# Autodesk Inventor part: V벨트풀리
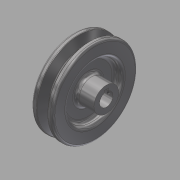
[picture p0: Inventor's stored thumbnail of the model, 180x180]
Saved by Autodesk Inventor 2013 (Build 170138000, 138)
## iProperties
Created: 2015-11
Part Number: V벨트풀리
Material: 강철, 탄소
Document SubType Name: Modeling
Designer: mduedu
Density: 1 g/cm^3
Author: mduedu
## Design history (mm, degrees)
sketch "스케치1"
  geometry: L1 (-9.5, 0)-(9.5, 0); L2 (0, 0)-(0, 37.7); L3 (-4.825, 37.7)-(-9.5, 37.7); L4 (-9.5, 37.7)-(-9.5, 0); L5 (0, 28.7)-(-2.074, 28.7); L6 (-2.074, 28.7)-(-4.825, 37.7); L7 (4.825, 37.7)-(9.5, 37.7); L8 (9.5, 37.7)-(9.5, 0); L9 (0, 28.7)-(2.074, 28.7); L10 (2.074, 28.7)-(4.825, 37.7); L11 (-9.5, 35)-(9.5, 35); 3 further points
  constraints: 22 end point, 7 point on line, 4 perpendicular, 3 symmetric about line, 1 coincident, 1 horizontal, 1 horizontal alignment, 1 midpoint, 1 vertical
  dimensions: "d0" = 19 distance of L1.start L1.end; "d2" = 75.4 diameter of L2.end L1 (derived); "d3" = 34 deg angle of L10 L6; "d4" = 6.3 distance between parallel lines of L11 L9; "d5" = 2.7 distance between parallel lines of L7 L11; "d6" = 8 distance of point (4, 35) point (-4, 35); "d7" = 70 diameter of L11 L1
revolve "회전1" sketch "스케치1" stored, may be unused: angle "d8" = 90 deg
sketch "스케치2"
  geometry: C1 r 24 at (0, 0); C2 r 11 at (0, 0); 1 further point
  constraints: 2 centre point, 2 coincident
  dimensions: "d9" = 48 diameter of C1; "d10" = 22 diameter of C2
extrude "돌출1" cut sketch "스케치2" distance "d11" = 6; taper "d12" = 0 deg
extrude "돌출3" join sketch "스케치2" distance "d37" = 10; taper "d38" = 0 deg
fillet "모깎기1" dims "d13" = 3
fillet "모깎기2" dims "d14" = 3
fillet "모깎기3" dims "d15" = 1, "d16" = 0.5, "d17" = 2
hole "구멍1" diameter "d20" = 12; stored, may be unused: countersink angle "d24" = 90 deg, drill point angle "d26" = 118 deg; dims "d21" = 6, "d22" = 4, "d23" = 2, "d25" = 8, "d39" = 10, "d40" = 10
sketch "스케치3"
  geometry: L1 (-2, 0)-(2, 0); L2 (2, 0)-(2, 7.8); L3 (2, 7.8)-(-2, 7.8); L4 (-2, 7.8)-(-2, 0); 2 further points
  constraints: 8 end point, 2 parallel, 1 coincident, 1 horizontal, 1 midpoint, 1 perpendicular
  dimensions: "d27" = 4 distance of L2.end L3.end; "d29" = 7.8 distance of L3.end L1.start
extrude "돌출2" cut sketch "스케치3" stored distance "d30" = 6; taper "d31" = 0 deg
chamfer "모따기1" distance "d32" = 0.5; stored, may be unused: second distance "d33" = 2, angle "d34" = 45 deg
node "작업 평면1"
sketch "스케치4"
  geometry: L1 (-19, 11)-(-19, -11) reference; 2 further points
  constraints: 1 horizontal alignment
  dimensions: "d41" = 25 distance from line of point (6, 0) L1
hole "구멍2" sketch "스케치4" at (6, 0) diameter "d42" = 2.459; stored, may be unused: countersink angle "d46" = 90 deg, drill point angle "d48" = 118 deg; dims "d43" = 6, "d44" = 4, "d45" = 2, "d47" = 8
node "솔리드1"
mirror "대칭1"
